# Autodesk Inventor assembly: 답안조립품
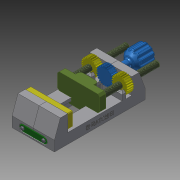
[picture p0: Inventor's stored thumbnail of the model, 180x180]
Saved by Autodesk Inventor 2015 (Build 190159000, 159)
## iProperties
Created: 2017-04
Part Number: 답안조립품
Document SubType Name: Assembly
Designer: owner
Mass: 1269.82 g
Surface Area: 784.421 cm^2
Volume: 280.831 cm^3
Density: 4.52164 g/cm^3
Author: owner
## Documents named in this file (10)
- C:\Users\owner\Desktop\370407V1013\답안조립품.iam
- C:\Users\owner\Desktop\370407V1013\바이스본체 A.ipt
- C:\Users\owner\Desktop\370407V1013\고정 플레이트.ipt
- C:\Users\owner\Desktop\370407V1013\바이스본체 B.ipt
- C:\Users\owner\Desktop\370407V1013\스퍼기어.ipt
- C:\Users\owner\Desktop\370407V1013\슬라이딩 부품.ipt
- C:\Users\owner\Desktop\370407V1013\십자오목머리나사 M3.ipt
- C:\Users\owner\Desktop\370407V1013\십자오목머리나사 M4.ipt
- C:\Users\owner\Desktop\370407V1013\지지대.ipt
- C:\Users\owner\Desktop\370407V1013\핸들.ipt
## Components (3 placed, 2 different names)
1. 고정 플레이트:1 — 각도:2
2. 핸들:1
3. 고정 플레이트:2 — 각도:1
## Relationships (2: Angle 2)
- 각도:1 [Angle]: 고정 플레이트:2
- 각도:2 [Angle]: 고정 플레이트:1
